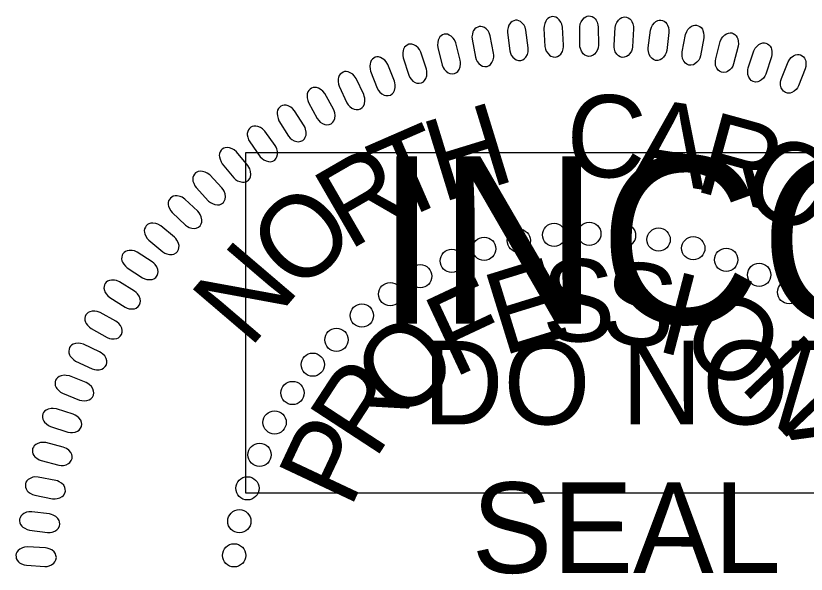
# Model space of a CAD drawing. Extents: x 505602 to 507286, y 483109 to 484209.
# Drawn here: x 507079.7 to 507134.2, y 484096.9 to 484135.4 of the extents above; entities that cross this region are included whole.
import ezdxf

# ---------------------------------------------------------------- set-up
doc = ezdxf.new("R2010")
doc.units = 0
doc.layers.add('Sheet PE Seal Cell', color=7, linetype='Continuous')
doc.layers.add('Sheet Sticker Incomplete CELL', color=7, linetype='Continuous')

msp = doc.modelspace()

# ---------------------------------------------------------------- linework, layer by layer
at = {"layer": 'Sheet PE Seal Cell'}
for points in [[(507117.5, 484133.403), (507117.423, 484134.628), (507117.372, 484134.844), (507117.311, 484134.98), (507117.188, 484135.143), (507117.085, 484135.246), (507116.968, 484135.319), (507116.861, 484135.352), (507116.747, 484135.364), (507116.637, 484135.337), (507116.52, 484135.3), (507116.419, 484135.234), (507116.321, 484135.128), (507116.266, 484135.045), (507116.208, 484134.891), (507116.159, 484134.708), (507116.147, 484134.548), (507116.218, 484133.293), (507116.251, 484133.125), (507116.305, 484132.989), (507116.404, 484132.835), (507116.525, 484132.703), (507116.626, 484132.629), (507116.787, 484132.579), (507116.938, 484132.568), (507117.085, 484132.618), (507117.186, 484132.674), (507117.306, 484132.782), (507117.415, 484132.958), (507117.471, 484133.142), (507117.493, 484133.273)], [(507118.615, 484133.412), (507118.615, 484134.639), (507118.653, 484134.858), (507118.705, 484134.998), (507118.817, 484135.167), (507118.915, 484135.277), (507119.027, 484135.357), (507119.131, 484135.397), (507119.244, 484135.417), (507119.355, 484135.397), (507119.475, 484135.367), (507119.58, 484135.307), (507119.684, 484135.207), (507119.744, 484135.127), (507119.811, 484134.977), (507119.871, 484134.798), (507119.894, 484134.638), (507119.901, 484133.382), (507119.878, 484133.212), (507119.833, 484133.073), (507119.744, 484132.913), (507119.631, 484132.773), (507119.534, 484132.694), (507119.377, 484132.634), (507119.228, 484132.614), (507119.078, 484132.654), (507118.974, 484132.704), (507118.846, 484132.803), (507118.727, 484132.974), (507118.66, 484133.153), (507118.63, 484133.283)], [(507120.974, 484133.386), (507121.051, 484134.61), (507121.102, 484134.827), (507121.163, 484134.963), (507121.286, 484135.125), (507121.39, 484135.228), (507121.507, 484135.301), (507121.614, 484135.334), (507121.727, 484135.347), (507121.838, 484135.319), (507121.955, 484135.282), (507122.056, 484135.216), (507122.154, 484135.11), (507122.209, 484135.026), (507122.267, 484134.873), (507122.315, 484134.69), (507122.327, 484134.53), (507122.255, 484133.275), (507122.222, 484133.107), (507122.169, 484132.97), (507122.069, 484132.817), (507121.948, 484132.685), (507121.846, 484132.611), (507121.686, 484132.561), (507121.535, 484132.55), (507121.389, 484132.6), (507121.287, 484132.657), (507121.167, 484132.764), (507121.059, 484132.941), (507121.002, 484133.124), (507120.981, 484133.256)], [(507112.68, 484132.833), (507112.451, 484134.037), (507112.373, 484134.246), (507112.296, 484134.374), (507112.153, 484134.519), (507112.038, 484134.608), (507111.913, 484134.666), (507111.803, 484134.685), (507111.688, 484134.684), (507111.582, 484134.644), (507111.47, 484134.592), (507111.378, 484134.514), (507111.294, 484134.396), (507111.25, 484134.306), (507111.213, 484134.147), (507111.187, 484133.959), (507111.195, 484133.798), (507111.423, 484132.563), (507111.476, 484132.4), (507111.546, 484132.271), (507111.665, 484132.131), (507111.801, 484132.015), (507111.911, 484131.955), (507112.077, 484131.926), (507112.227, 484131.934), (507112.367, 484132.001), (507112.46, 484132.07), (507112.566, 484132.191), (507112.652, 484132.38), (507112.685, 484132.569), (507112.689, 484132.702)], [(507115.061, 484133.201), (507114.908, 484134.418), (507114.844, 484134.631), (507114.774, 484134.762), (507114.642, 484134.917), (507114.531, 484135.013), (507114.411, 484135.079), (507114.301, 484135.105), (507114.187, 484135.111), (507114.079, 484135.077), (507113.964, 484135.032), (507113.868, 484134.96), (507113.776, 484134.848), (507113.727, 484134.761), (507113.679, 484134.605), (507113.642, 484134.419), (507113.64, 484134.258), (507113.79, 484133.01), (507113.833, 484132.845), (507113.895, 484132.712), (507114.003, 484132.565), (507114.132, 484132.44), (507114.239, 484132.373), (507114.402, 484132.333), (507114.553, 484132.332), (507114.696, 484132.391), (507114.794, 484132.453), (507114.907, 484132.568), (507115.005, 484132.751), (507115.049, 484132.937), (507115.062, 484133.07)], [(507123.336, 484133.211), (507123.491, 484134.427), (507123.555, 484134.641), (507123.625, 484134.772), (507123.757, 484134.926), (507123.868, 484135.023), (507123.989, 484135.088), (507124.097, 484135.115), (507124.211, 484135.12), (507124.32, 484135.086), (507124.434, 484135.042), (507124.531, 484134.969), (507124.622, 484134.857), (507124.672, 484134.771), (507124.72, 484134.613), (507124.756, 484134.428), (507124.759, 484134.267), (507124.608, 484133.019), (507124.564, 484132.854), (507124.503, 484132.721), (507124.394, 484132.574), (507124.265, 484132.45), (507124.159, 484132.383), (507123.995, 484132.343), (507123.844, 484132.342), (507123.701, 484132.4), (507123.603, 484132.463), (507123.489, 484132.578), (507123.392, 484132.761), (507123.348, 484132.948), (507123.335, 484133.08)], [(507125.676, 484132.924), (507125.906, 484134.129), (507125.984, 484134.337), (507126.062, 484134.464), (507126.204, 484134.61), (507126.319, 484134.699), (507126.444, 484134.757), (507126.555, 484134.776), (507126.669, 484134.775), (507126.775, 484134.735), (507126.887, 484134.683), (507126.979, 484134.604), (507127.063, 484134.486), (507127.106, 484134.397), (507127.144, 484134.237), (507127.17, 484134.05), (507127.162, 484133.889), (507126.933, 484132.653), (507126.879, 484132.491), (507126.809, 484132.362), (507126.691, 484132.222), (507126.554, 484132.106), (507126.444, 484132.046), (507126.279, 484132.017), (507126.128, 484132.025), (507125.989, 484132.092), (507125.896, 484132.161), (507125.789, 484132.283), (507125.704, 484132.472), (507125.671, 484132.661), (507125.666, 484132.794)], [(507110.375, 484132.36), (507110.07, 484133.548), (507109.98, 484133.752), (507109.894, 484133.874), (507109.743, 484134.01), (507109.622, 484134.092), (507109.494, 484134.142), (507109.382, 484134.155), (507109.269, 484134.146), (507109.165, 484134.099), (507109.057, 484134.04), (507108.97, 484133.956), (507108.893, 484133.834), (507108.855, 484133.742), (507108.827, 484133.58), (507108.814, 484133.391), (507108.832, 484133.231), (507109.137, 484132.012), (507109.2, 484131.854), (507109.279, 484131.729), (507109.405, 484131.597), (507109.549, 484131.489), (507109.662, 484131.437), (507109.83, 484131.417), (507109.979, 484131.435), (507110.114, 484131.511), (507110.203, 484131.585), (507110.301, 484131.714), (507110.375, 484131.907), (507110.396, 484132.098), (507110.392, 484132.231)], [(507127.981, 484132.45), (507128.286, 484133.638), (507128.377, 484133.841), (507128.463, 484133.964), (507128.614, 484134.1), (507128.735, 484134.182), (507128.863, 484134.231), (507128.975, 484134.244), (507129.089, 484134.236), (507129.192, 484134.189), (507129.3, 484134.129), (507129.387, 484134.046), (507129.463, 484133.923), (507129.501, 484133.831), (507129.529, 484133.669), (507129.543, 484133.48), (507129.525, 484133.32), (507129.219, 484132.101), (507129.154, 484131.943), (507129.076, 484131.819), (507128.95, 484131.687), (507128.806, 484131.579), (507128.693, 484131.526), (507128.526, 484131.507), (507128.376, 484131.525), (507128.241, 484131.601), (507128.152, 484131.675), (507128.054, 484131.803), (507127.98, 484131.998), (507127.96, 484132.188), (507127.963, 484132.321)], [(507130.231, 484131.828), (507130.61, 484132.995), (507130.714, 484133.192), (507130.807, 484133.308), (507130.966, 484133.435), (507131.092, 484133.509), (507131.223, 484133.551), (507131.335, 484133.556), (507131.448, 484133.54), (507131.549, 484133.487), (507131.653, 484133.421), (507131.735, 484133.332), (507131.803, 484133.205), (507131.835, 484133.11), (507131.853, 484132.947), (507131.854, 484132.758), (507131.826, 484132.599), (507131.444, 484131.402), (507131.371, 484131.248), (507131.285, 484131.129), (507131.15, 484131.004), (507131, 484130.907), (507130.883, 484130.861), (507130.715, 484130.853), (507130.567, 484130.88), (507130.437, 484130.964), (507130.353, 484131.044), (507130.263, 484131.178), (507130.202, 484131.376), (507130.193, 484131.568), (507130.205, 484131.7)], [(507108.041, 484131.74), (507107.662, 484132.906), (507107.56, 484133.103), (507107.467, 484133.22), (507107.308, 484133.347), (507107.181, 484133.422), (507107.05, 484133.463), (507106.938, 484133.468), (507106.825, 484133.453), (507106.724, 484133.399), (507106.621, 484133.334), (507106.539, 484133.245), (507106.47, 484133.118), (507106.438, 484133.023), (507106.42, 484132.86), (507106.419, 484132.671), (507106.447, 484132.512), (507106.827, 484131.314), (507106.901, 484131.16), (507106.987, 484131.041), (507107.121, 484130.917), (507107.271, 484130.819), (507107.388, 484130.773), (507107.556, 484130.765), (507107.704, 484130.792), (507107.834, 484130.876), (507107.919, 484130.956), (507108.009, 484131.09), (507108.07, 484131.288), (507108.079, 484131.479), (507108.067, 484131.612)], [(507105.84, 484130.923), (507105.389, 484132.064), (507105.273, 484132.254), (507105.174, 484132.365), (507105.007, 484132.481), (507104.876, 484132.548), (507104.743, 484132.58), (507104.631, 484132.579), (507104.519, 484132.556), (507104.422, 484132.496), (507104.322, 484132.425), (507104.247, 484132.331), (507104.186, 484132.199), (507104.16, 484132.103), (507104.152, 484131.939), (507104.163, 484131.75), (507104.2, 484131.594), (507104.656, 484130.423), (507104.739, 484130.273), (507104.832, 484130.16), (507104.974, 484130.044), (507105.13, 484129.956), (507105.249, 484129.917), (507105.418, 484129.919), (507105.564, 484129.956), (507105.688, 484130.049), (507105.767, 484130.133), (507105.849, 484130.273), (507105.898, 484130.474), (507105.894, 484130.666), (507105.874, 484130.797)], [(507132.514, 484131.093), (507132.966, 484132.234), (507133.082, 484132.424), (507133.182, 484132.535), (507133.349, 484132.651), (507133.48, 484132.717), (507133.613, 484132.75), (507133.725, 484132.748), (507133.837, 484132.726), (507133.933, 484132.666), (507134.034, 484132.594), (507134.109, 484132.5), (507134.17, 484132.368), (507134.196, 484132.272), (507134.203, 484132.109), (507134.193, 484131.919), (507134.155, 484131.763), (507133.699, 484130.592), (507133.615, 484130.443), (507133.522, 484130.329), (507133.38, 484130.214), (507133.224, 484130.125), (507133.105, 484130.087), (507132.936, 484130.09), (507132.79, 484130.126), (507132.666, 484130.218), (507132.587, 484130.303), (507132.505, 484130.442), (507132.457, 484130.644), (507132.46, 484130.836), (507132.481, 484130.968)], [(507103.723, 484129.99), (507103.201, 484131.101), (507103.074, 484131.283), (507102.967, 484131.387), (507102.794, 484131.494), (507102.659, 484131.551), (507102.523, 484131.575), (507102.412, 484131.567), (507102.302, 484131.537), (507102.209, 484131.472), (507102.113, 484131.394), (507102.044, 484131.295), (507101.992, 484131.16), (507101.972, 484131.063), (507101.974, 484130.899), (507101.997, 484130.711), (507102.044, 484130.557), (507102.572, 484129.417), (507102.665, 484129.272), (507102.765, 484129.165), (507102.914, 484129.059), (507103.075, 484128.98), (507103.196, 484128.95), (507103.364, 484128.962), (507103.508, 484129.008), (507103.626, 484129.108), (507103.7, 484129.197), (507103.772, 484129.341), (507103.808, 484129.545), (507103.793, 484129.737), (507103.765, 484129.867)], [(507101.64, 484128.976), (507101.049, 484130.052), (507100.911, 484130.226), (507100.798, 484130.323), (507100.618, 484130.418), (507100.48, 484130.467), (507100.343, 484130.483), (507100.233, 484130.468), (507100.124, 484130.431), (507100.036, 484130.36), (507099.945, 484130.276), (507099.882, 484130.173), (507099.839, 484130.035), (507099.825, 484129.937), (507099.837, 484129.773), (507099.872, 484129.587), (507099.929, 484129.436), (507100.528, 484128.331), (507100.628, 484128.194), (507100.735, 484128.093), (507100.89, 484127.996), (507101.056, 484127.928), (507101.18, 484127.905), (507101.346, 484127.928), (507101.486, 484127.982), (507101.599, 484128.089), (507101.666, 484128.183), (507101.73, 484128.332), (507101.753, 484128.538), (507101.726, 484128.728), (507101.689, 484128.856)], [(507099.622, 484127.834), (507098.965, 484128.87), (507098.816, 484129.036), (507098.698, 484129.126), (507098.512, 484129.209), (507098.371, 484129.249), (507098.234, 484129.257), (507098.124, 484129.235), (507098.019, 484129.191), (507097.934, 484129.115), (507097.85, 484129.025), (507097.793, 484128.919), (507097.758, 484128.778), (507097.751, 484128.679), (507097.774, 484128.516), (507097.82, 484128.333), (507097.886, 484128.186), (507098.553, 484127.121), (507098.662, 484126.989), (507098.775, 484126.895), (507098.937, 484126.809), (507099.106, 484126.751), (507099.23, 484126.735), (507099.395, 484126.769), (507099.532, 484126.833), (507099.637, 484126.946), (507099.699, 484127.045), (507099.753, 484127.196), (507099.763, 484127.404), (507099.723, 484127.592), (507099.679, 484127.717)], [(507097.622, 484126.48), (507096.901, 484127.473), (507096.742, 484127.628), (507096.618, 484127.711), (507096.427, 484127.782), (507096.284, 484127.813), (507096.147, 484127.812), (507096.038, 484127.783), (507095.936, 484127.733), (507095.857, 484127.651), (507095.778, 484127.557), (507095.728, 484127.447), (507095.702, 484127.305), (507095.7, 484127.205), (507095.734, 484127.044), (507095.791, 484126.864), (507095.867, 484126.722), (507096.599, 484125.7), (507096.717, 484125.576), (507096.835, 484125.489), (507097.001, 484125.413), (507097.174, 484125.366), (507097.3, 484125.358), (507097.462, 484125.403), (507097.594, 484125.474), (507097.692, 484125.594), (507097.747, 484125.696), (507097.792, 484125.851), (507097.789, 484126.059), (507097.738, 484126.244), (507097.686, 484126.366)], [(507095.741, 484125.091), (507094.959, 484126.036), (507094.791, 484126.181), (507094.662, 484126.256), (507094.468, 484126.315), (507094.323, 484126.338), (507094.185, 484126.328), (507094.08, 484126.292), (507093.98, 484126.235), (507093.906, 484126.149), (507093.834, 484126.049), (507093.79, 484125.937), (507093.774, 484125.793), (507093.778, 484125.694), (507093.822, 484125.535), (507093.89, 484125.359), (507093.975, 484125.221), (507094.769, 484124.248), (507094.895, 484124.132), (507095.018, 484124.053), (507095.189, 484123.987), (507095.364, 484123.951), (507095.49, 484123.951), (507095.649, 484124.005), (507095.777, 484124.086), (507095.867, 484124.212), (507095.916, 484124.316), (507095.95, 484124.474), (507095.934, 484124.681), (507095.872, 484124.862), (507095.812, 484124.981)], [(507093.954, 484123.552), (507093.114, 484124.446), (507092.937, 484124.581), (507092.803, 484124.647), (507092.605, 484124.694), (507092.46, 484124.708), (507092.323, 484124.689), (507092.219, 484124.646), (507092.124, 484124.584), (507092.056, 484124.493), (507091.989, 484124.389), (507091.954, 484124.274), (507091.946, 484124.129), (507091.956, 484124.03), (507092.01, 484123.875), (507092.089, 484123.704), (507092.181, 484123.572), (507093.037, 484122.65), (507093.169, 484122.542), (507093.297, 484122.471), (507093.472, 484122.416), (507093.65, 484122.391), (507093.775, 484122.399), (507093.93, 484122.463), (507094.053, 484122.551), (507094.134, 484122.682), (507094.177, 484122.79), (507094.201, 484122.95), (507094.173, 484123.155), (507094.098, 484123.332), (507094.032, 484123.447)], [(507092.291, 484121.943), (507091.398, 484122.782), (507091.212, 484122.906), (507091.074, 484122.963), (507090.874, 484122.998), (507090.728, 484123.002), (507090.592, 484122.975), (507090.492, 484122.926), (507090.401, 484122.858), (507090.339, 484122.763), (507090.278, 484122.655), (507090.25, 484122.538), (507090.251, 484122.393), (507090.268, 484122.295), (507090.331, 484122.143), (507090.421, 484121.977), (507090.522, 484121.851), (507091.433, 484120.985), (507091.571, 484120.886), (507091.704, 484120.822), (507091.882, 484120.779), (507092.06, 484120.765), (507092.185, 484120.781), (507092.336, 484120.854), (507092.453, 484120.95), (507092.526, 484121.086), (507092.561, 484121.196), (507092.576, 484121.357), (507092.534, 484121.561), (507092.45, 484121.732), (507092.376, 484121.843)], [(507090.678, 484120.156), (507089.733, 484120.938), (507089.54, 484121.049), (507089.399, 484121.098), (507089.197, 484121.12), (507089.051, 484121.115), (507088.918, 484121.079), (507088.821, 484121.024), (507088.734, 484120.95), (507088.677, 484120.851), (507088.625, 484120.74), (507088.603, 484120.621), (507088.614, 484120.477), (507088.637, 484120.38), (507088.709, 484120.233), (507088.81, 484120.072), (507088.918, 484119.953), (507089.881, 484119.146), (507090.026, 484119.055), (507090.162, 484119.001), (507090.343, 484118.968), (507090.521, 484118.966), (507090.645, 484118.99), (507090.791, 484119.073), (507090.901, 484119.175), (507090.966, 484119.315), (507090.995, 484119.428), (507090.999, 484119.589), (507090.945, 484119.789), (507090.849, 484119.956), (507090.768, 484120.061)], [(507089.153, 484118.454), (507088.123, 484119.119), (507087.918, 484119.207), (507087.773, 484119.239), (507087.57, 484119.237), (507087.425, 484119.215), (507087.297, 484119.164), (507087.207, 484119.098), (507087.129, 484119.014), (507087.085, 484118.909), (507087.046, 484118.792), (507087.038, 484118.672), (507087.066, 484118.53), (507087.1, 484118.436), (507087.189, 484118.299), (507087.308, 484118.151), (507087.429, 484118.046), (507088.481, 484117.357), (507088.635, 484117.284), (507088.777, 484117.246), (507088.96, 484117.235), (507089.138, 484117.253), (507089.258, 484117.292), (507089.393, 484117.391), (507089.491, 484117.506), (507089.538, 484117.653), (507089.553, 484117.768), (507089.539, 484117.929), (507089.461, 484118.121), (507089.347, 484118.275), (507089.254, 484118.37)], [(507087.939, 484116.431), (507086.904, 484117.088), (507086.699, 484117.174), (507086.553, 484117.205), (507086.349, 484117.202), (507086.204, 484117.178), (507086.077, 484117.127), (507085.987, 484117.059), (507085.91, 484116.975), (507085.867, 484116.87), (507085.828, 484116.753), (507085.822, 484116.633), (507085.851, 484116.491), (507085.886, 484116.397), (507085.976, 484116.26), (507086.095, 484116.114), (507086.218, 484116.01), (507087.275, 484115.329), (507087.43, 484115.258), (507087.572, 484115.22), (507087.755, 484115.211), (507087.933, 484115.23), (507088.052, 484115.269), (507088.187, 484115.37), (507088.284, 484115.486), (507088.33, 484115.633), (507088.344, 484115.748), (507088.328, 484115.909), (507088.25, 484116.1), (507088.134, 484116.254), (507088.04, 484116.349)], [(507086.636, 484114.381), (507085.561, 484114.973), (507085.351, 484115.046), (507085.203, 484115.068), (507085, 484115.051), (507084.857, 484115.018), (507084.733, 484114.959), (507084.648, 484114.886), (507084.576, 484114.798), (507084.54, 484114.69), (507084.509, 484114.571), (507084.51, 484114.45), (507084.548, 484114.311), (507084.589, 484114.22), (507084.687, 484114.089), (507084.816, 484113.95), (507084.945, 484113.853), (507086.042, 484113.241), (507086.201, 484113.179), (507086.345, 484113.151), (507086.528, 484113.152), (507086.705, 484113.183), (507086.822, 484113.23), (507086.95, 484113.339), (507087.039, 484113.46), (507087.076, 484113.61), (507087.083, 484113.726), (507087.057, 484113.886), (507086.966, 484114.072), (507086.841, 484114.217), (507086.742, 484114.306)], [(507085.527, 484112.258), (507084.417, 484112.78), (507084.203, 484112.84), (507084.054, 484112.853), (507083.853, 484112.823), (507083.712, 484112.782), (507083.592, 484112.714), (507083.511, 484112.637), (507083.446, 484112.544), (507083.416, 484112.434), (507083.392, 484112.313), (507083.401, 484112.193), (507083.447, 484112.056), (507083.494, 484111.968), (507083.601, 484111.843), (507083.738, 484111.712), (507083.872, 484111.624), (507085.007, 484111.081), (507085.169, 484111.03), (507085.314, 484111.012), (507085.497, 484111.024), (507085.671, 484111.066), (507085.784, 484111.12), (507085.906, 484111.236), (507085.988, 484111.363), (507086.015, 484111.516), (507086.014, 484111.632), (507085.978, 484111.789), (507085.876, 484111.97), (507085.742, 484112.106), (507085.637, 484112.189)], [(507084.587, 484110.139), (507083.447, 484110.591), (507083.229, 484110.636), (507083.08, 484110.64), (507082.881, 484110.598), (507082.743, 484110.548), (507082.628, 484110.473), (507082.553, 484110.39), (507082.492, 484110.293), (507082.47, 484110.182), (507082.454, 484110.059), (507082.47, 484109.941), (507082.525, 484109.807), (507082.577, 484109.721), (507082.691, 484109.604), (507082.836, 484109.483), (507082.976, 484109.402), (507084.141, 484108.933), (507084.307, 484108.891), (507084.454, 484108.881), (507084.635, 484108.906), (507084.806, 484108.959), (507084.916, 484109.02), (507085.03, 484109.143), (507085.103, 484109.275), (507085.121, 484109.428), (507085.113, 484109.545), (507085.068, 484109.699), (507084.954, 484109.873), (507084.812, 484110.001), (507084.702, 484110.077)], [(507083.712, 484107.95), (507082.545, 484108.329), (507082.325, 484108.361), (507082.176, 484108.355), (507081.98, 484108.301), (507081.845, 484108.242), (507081.735, 484108.16), (507081.665, 484108.073), (507081.611, 484107.972), (507081.596, 484107.86), (507081.587, 484107.737), (507081.611, 484107.619), (507081.674, 484107.488), (507081.732, 484107.407), (507081.853, 484107.296), (507082.005, 484107.184), (507082.15, 484107.114), (507083.342, 484106.717), (507083.51, 484106.687), (507083.657, 484106.686), (507083.837, 484106.722), (507084.004, 484106.786), (507084.111, 484106.853), (507084.216, 484106.984), (507084.281, 484107.12), (507084.289, 484107.275), (507084.274, 484107.389), (507084.219, 484107.541), (507084.094, 484107.707), (507083.944, 484107.827), (507083.83, 484107.895)], [(507083.007, 484105.694), (507081.819, 484105.999), (507081.598, 484106.018), (507081.449, 484106.002), (507081.257, 484105.936), (507081.126, 484105.869), (507081.021, 484105.78), (507080.957, 484105.689), (507080.909, 484105.585), (507080.9, 484105.472), (507080.9, 484105.348), (507080.931, 484105.232), (507081.002, 484105.106), (507081.064, 484105.028), (507081.193, 484104.925), (507081.352, 484104.823), (507081.501, 484104.762), (507082.716, 484104.441), (507082.886, 484104.421), (507083.032, 484104.43), (507083.209, 484104.477), (507083.372, 484104.55), (507083.474, 484104.625), (507083.571, 484104.762), (507083.627, 484104.902), (507083.626, 484105.056), (507083.603, 484105.17), (507083.539, 484105.318), (507083.404, 484105.476), (507083.247, 484105.586), (507083.128, 484105.647)], [(507082.496, 484103.398), (507081.291, 484103.628), (507081.069, 484103.633), (507080.921, 484103.609), (507080.734, 484103.53), (507080.608, 484103.455), (507080.508, 484103.359), (507080.45, 484103.265), (507080.409, 484103.158), (507080.408, 484103.044), (507080.415, 484102.921), (507080.453, 484102.807), (507080.532, 484102.686), (507080.599, 484102.612), (507080.733, 484102.517), (507080.899, 484102.425), (507081.051, 484102.373), (507082.284, 484102.129), (507082.455, 484102.12), (507082.601, 484102.139), (507082.774, 484102.196), (507082.932, 484102.28), (507083.029, 484102.361), (507083.117, 484102.504), (507083.165, 484102.647), (507083.154, 484102.801), (507083.124, 484102.913), (507083.05, 484103.057), (507082.906, 484103.206), (507082.742, 484103.306), (507082.62, 484103.36)], [(507082.076, 484101.084), (507080.859, 484101.238), (507080.636, 484101.229), (507080.491, 484101.195), (507080.309, 484101.104), (507080.187, 484101.022), (507080.094, 484100.921), (507080.042, 484100.822), (507080.008, 484100.713), (507080.014, 484100.6), (507080.028, 484100.477), (507080.074, 484100.366), (507080.161, 484100.249), (507080.232, 484100.18), (507080.372, 484100.094), (507080.542, 484100.013), (507080.698, 484099.97), (507081.944, 484099.805), (507082.115, 484099.806), (507082.259, 484099.833), (507082.428, 484099.901), (507082.581, 484099.996), (507082.672, 484100.082), (507082.752, 484100.23), (507082.79, 484100.376), (507082.769, 484100.529), (507082.733, 484100.639), (507082.65, 484100.778), (507082.497, 484100.918), (507082.327, 484101.007), (507082.202, 484101.053)], [(507081.789, 484098.74), (507080.565, 484098.817), (507080.343, 484098.794), (507080.2, 484098.751), (507080.024, 484098.65), (507079.908, 484098.56), (507079.822, 484098.453), (507079.776, 484098.351), (507079.749, 484098.24), (507079.762, 484098.127), (507079.784, 484098.005), (507079.837, 484097.897), (507079.93, 484097.787), (507080.006, 484097.722), (507080.151, 484097.645), (507080.326, 484097.574), (507080.484, 484097.542), (507081.738, 484097.455), (507081.908, 484097.467), (507082.05, 484097.503), (507082.215, 484097.583), (507082.362, 484097.685), (507082.448, 484097.777), (507082.517, 484097.93), (507082.546, 484098.078), (507082.516, 484098.23), (507082.473, 484098.338), (507082.382, 484098.471), (507082.22, 484098.6), (507082.045, 484098.679), (507081.917, 484098.717)]]:
    msp.add_lwpolyline(points, close=True, dxfattribs=at)
for centre in [(507116.843, 484120.316), (507119.272, 484120.395), (507121.661, 484120.275), (507114.414, 484119.919), (507124.049, 484119.995), (507112.025, 484119.362), (507126.438, 484119.397), (507128.707, 484118.6), (507109.796, 484118.526), (507107.621, 484117.465), (507130.976, 484117.563), (507133.046, 484116.367), (507105.55, 484116.231), (507103.599, 484114.758), (507101.847, 484113.085), (507100.214, 484111.373), (507098.82, 484109.421), (507097.585, 484107.39), (507096.549, 484105.159), (507095.712, 484102.849), (507095.154, 484100.578), (507094.795, 484098.228)]:
    msp.add_circle(centre, 0.801, dxfattribs=at)
at = {"layer": 'Sheet Sticker Incomplete CELL'}
msp.add_lwpolyline([(507095.597, 484102.505), (507095.597, 484126.005), (507242.597, 484126.005), (507242.597, 484102.505)], close=True, dxfattribs=at)

# ---------------------------------------------------------------- texts
at = {"layer": 'Sheet PE Seal Cell'}
for s, height, rotation, p in [('C', 5.669, 357.5877, (507117.59, 484124.407)), ('H', 5.669, 17.0557, (507109.084, 484122.523)), ('A', 5.669, 351.0983, (507122.165, 484124.198)), ('R', 5.669, 344.609, (507126.371, 484123.404)), ('T', 5.669, 23.5451, (507105.906, 484121.113)), ('O', 5.669, 331.6302, (507129.326, 484122.75)), ('R', 5.669, 30.0345, (507102.685, 484119.195)), ('O', 5.669, 43.0132, (507099.209, 484116.166)), ('N', 5.669, 49.5025, (507095.863, 484112.411)), ('E', 5.669, 17.1686, (507113.281, 484111.954)), ('S', 5.669, 1.289, (507116.048, 484112.914)), ('S', 5.669, 353.3492, (507119.909, 484113.015)), ('F', 5.669, 25.1084, (507109.891, 484110.416)), ('I', 5.669, 345.4094, (507123.709, 484112.383)), ('O', 5.669, 329.5298, (507125.213, 484112.212)), ('O', 5.669, 40.988, (507106.194, 484107.277)), ('N', 5.669, 313.6502, (507129.525, 484109.907)), ('R', 5.669, 56.8676, (507104.48, 484104.731)), ('P', 5.669, 64.8074, (507102.793, 484101.369)), ('A', 5.669, 297.7707, (507132.862, 484106.827)), ('SEAL', 6.2363, 359.9814, (507111.164, 484097.02))]:
    msp.add_text(s, height=height, rotation=rotation, dxfattribs=at).set_placement(p)
at = {"layer": 'Sheet Sticker Incomplete CELL'}
for s, height, p in [('INCOMPLETE PLANS', 11.52, (507104.547, 484114.205)), ('DO NOT USE FOR R/W ACQUISITION', 5.76, (507107.797, 484107.255))]:
    msp.add_text(s, height=height, dxfattribs=at).set_placement(p)

doc.saveas('drawing.dxf')
